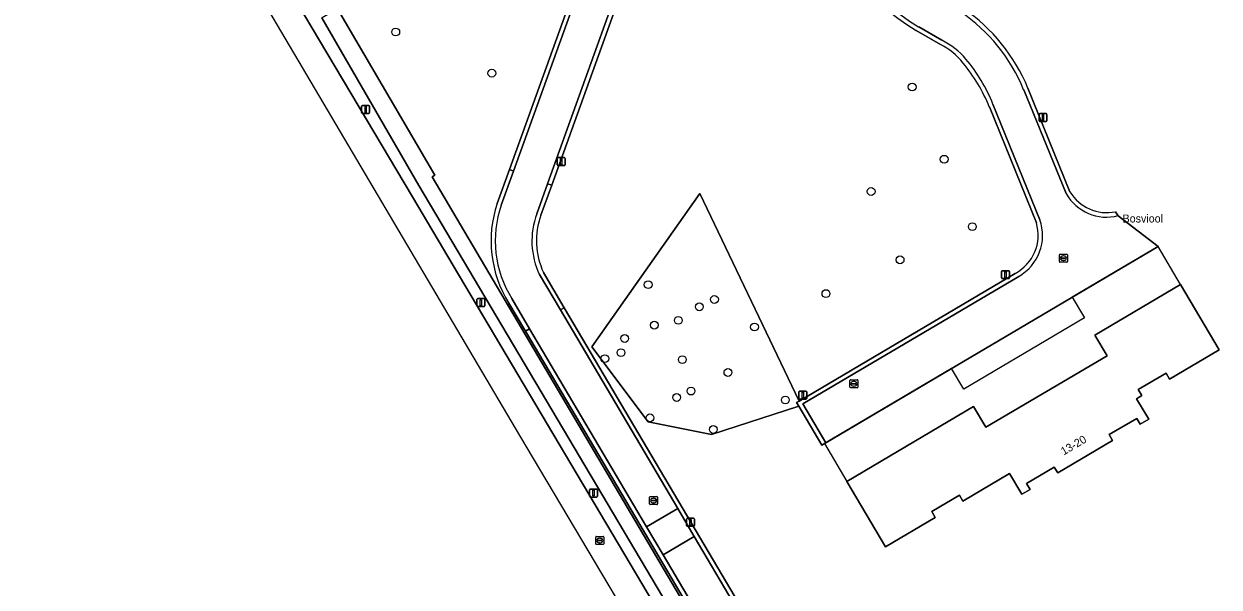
# Model space of a CAD drawing. Extents: x 156661 to 157576, y 383570 to 384425.
# Drawn here: x 156666.5 to 156815.9, y 383749.6 to 383820 of the extents above; entities that cross this region are included whole.
import ezdxf

# ---------------------------------------------------------------- set-up
doc = ezdxf.new("R2010")
doc.units = 0
for name, color, linetype in [('IMGEO_Boom', 7, 'Continuous'), ('IMGEO_Groenvoorziening', 7, 'Continuous'), ('IMGEO_Lichtmast', 7, 'Continuous'), ('IMGEO_Openbare_ruimte_label', 7, 'Continuous'), ('IMGEO_OVBaan_gesloten', 7, 'Continuous'), ('IMGEO_Pand', 7, 'Continuous'), ('IMGEO_Pand_nummerreeks', 7, 'Continuous'), ('IMGEO_Pand_overbouw', 7, 'Continuous'), ('IMGEO_Rijbaan_lokaal_gesloten', 7, 'Continuous'), ('IMGEO_Rijbaan_lokaal_halfverhard', 7, 'Continuous'), ('IMGEO_Rijbaan_lokaal_open', 7, 'Continuous'), ('IMGEO_Rioolput', 7, 'Continuous')]:
    doc.layers.add(name, color=color, linetype=linetype)

msp = doc.modelspace()

# ---------------------------------------------------------------- linework, layer by layer
at = {"layer": 'IMGEO_Boom'}
for centre in [(156712.98, 383818.98), (156724.99, 383813.83), (156777.53, 383812.1), (156781.53, 383803.07), (156772.4, 383799.04), (156785.05, 383794.64), (156776.02, 383790.49), (156744.54, 383787.39), (156766.75, 383786.27), (156750.93, 383784.62), (156752.82, 383785.54), (156745.31, 383782.32), (156748.3, 383782.92), (156757.82, 383782.1), (156741.59, 383780.66), (156741.13, 383778.89), (156739.12, 383778.14), (156748.8, 383778.01), (156754.5, 383776.41), (156749.89, 383774.08), (156748.09, 383773.28), (156761.67, 383772.97), (156744.76, 383770.73), (156752.67, 383769.28)]:
    msp.add_circle(centre, 0.489, dxfattribs=at)
at = {"layer": 'IMGEO_Groenvoorziening'}
for points in [[(156746.86, 383840.34), (156746.36, 383838.46), (156745.85, 383837.05), (156732.47, 383799.85), (156731.12, 383796.09)], [(156725.66, 383797.55), (156727.18, 383801.77), (156740.52, 383838.83)], [(156695.76, 383830.92), (156715.07, 383798.36), (156720.14, 383789.8), (156743.74, 383750), (156778.03, 383692.13), (156780.2, 383688.48), (156781.1, 383686.91)], [(156781.06, 383817.42), (156778.02, 383819.18)], [(156792.01, 383811.96), (156797.26, 383799.01)], [(156793.06, 383795.12), (156787.18, 383809.64)], [(156802.96, 383796.51), (156803.29, 383796.01), (156808.28, 383792.18), (156766.72, 383767.6), (156766.25, 383767.33), (156763.35, 383772.19), (156752.45, 383768.65), (156744.52, 383770.22), (156737.49, 383779.6), (156751, 383798.79), (156763.39, 383772.82), (156790.39, 383788.78)], [(156731.44, 383788.9), (156734.04, 383784.49), (156785.46, 383697.47), (156787.53, 383693.93)], [(156782.48, 383691.46), (156780.59, 383694.65), (156729.21, 383781.57), (156727.12, 383785.09)]]:
    msp.add_lwpolyline(points, dxfattribs=at)
for points in [[(156705.7, 383821.89), (156703.75, 383820.77), (156715.86, 383799.8), (156781.04, 383689.82), (156782.47, 383690.79), (156717.55, 383800.89), (156717.87, 383801.09)], [(156782.47, 383690.79), (156781.04, 383689.82), (156715.86, 383799.8), (156703.75, 383820.77), (156705.7, 383821.89), (156717.87, 383801.09), (156717.55, 383800.89)], [(156751, 383798.79), (156737.49, 383779.6), (156744.52, 383770.22), (156752.45, 383768.65), (156763.35, 383772.19), (156763.08, 383772.64), (156763.39, 383772.82)], [(156815.9, 383779.24), (156809.71, 383775.57), (156809.27, 383776.31), (156805.8, 383774.26), (156806.24, 383773.52), (156805.58, 383773.12), (156807.1, 383770.55), (156806.05, 383769.93), (156805.61, 383770.67), (156802.14, 383768.64), (156802.59, 383767.89), (156795.73, 383763.84), (156795.29, 383764.58), (156791.83, 383762.53), (156792.27, 383761.79), (156791.24, 383761.18), (156789.69, 383763.77), (156783.86, 383760.32), (156783.43, 383761.05), (156779.97, 383759.01), (156780.39, 383758.28), (156774.2, 383754.62), (156769.38, 383762.77), (156785.21, 383772.14), (156786.73, 383769.55), (156801.89, 383778.49), (156800.36, 383781.07), (156811.07, 383787.41)]]:
    msp.add_lwpolyline(points, close=True, dxfattribs=at)
for centre, radius, start, end in [((156793.47, 383844.76), 29.88, 157.8328, 238.869), ((156771.16, 383803.33), 22.56, 22.4904, 55.4335), ((156777.12, 383809.71), 8.66, 38.4985, 62.9776), ((156767.17, 383801.34), 21.66, 22.5311, 39.4519), ((156801.86, 383801.76), 5.36, 210.8749, 281.7523), ((156739.58, 383792.87), 14.69, 161.4197, 212.0138), ((156740.11, 383792.89), 9.54, 160.3934, 204.6888), ((156787.84, 383793.59), 5.44, 298.0182, 16.2918)]:
    msp.add_arc(centre, radius, start, end, dxfattribs=at)
at = {"layer": 'IMGEO_Lichtmast'}
for p, q in [((156708.72, 383808.9), (156708.72, 383809.7)), ((156708.72, 383809.7), (156708.72, 383808.9)), ((156708.82, 383809.8), (156709.61, 383809.8)), ((156709.61, 383809.8), (156708.82, 383809.8)), ((156709.71, 383809.7), (156709.71, 383808.9)), ((156709.71, 383808.9), (156709.71, 383809.7)), ((156709.61, 383808.8), (156708.82, 383808.8)), ((156708.82, 383808.8), (156709.61, 383808.8)), ((156793.39, 383807.89), (156793.39, 383808.68)), ((156793.39, 383808.68), (156793.39, 383807.89)), ((156793.49, 383808.78), (156794.28, 383808.78)), ((156794.28, 383808.78), (156793.49, 383808.78)), ((156794.28, 383807.79), (156793.49, 383807.79)), ((156793.49, 383807.79), (156794.28, 383807.79)), ((156794.38, 383808.68), (156794.38, 383807.89)), ((156794.38, 383807.89), (156794.38, 383808.68)), ((156733.17, 383802.38), (156733.17, 383803.18)), ((156733.17, 383803.18), (156733.17, 383802.38)), ((156733.27, 383803.28), (156734.06, 383803.28)), ((156734.06, 383803.28), (156733.27, 383803.28)), ((156734.16, 383803.18), (156734.16, 383802.38)), ((156734.16, 383802.38), (156734.16, 383803.18)), ((156734.06, 383802.28), (156733.27, 383802.28)), ((156733.27, 383802.28), (156734.06, 383802.28)), ((156788.7, 383788.24), (156788.7, 383789.03)), ((156788.7, 383789.03), (156788.7, 383788.24)), ((156788.8, 383789.13), (156789.59, 383789.13)), ((156789.59, 383789.13), (156788.8, 383789.13)), ((156789.59, 383788.14), (156788.8, 383788.14)), ((156788.8, 383788.14), (156789.59, 383788.14)), ((156789.69, 383789.03), (156789.69, 383788.24)), ((156789.69, 383788.24), (156789.69, 383789.03)), ((156723.13, 383784.74), (156723.13, 383785.54)), ((156723.13, 383785.54), (156723.13, 383784.74)), ((156723.23, 383785.64), (156724.01, 383785.64)), ((156724.01, 383785.64), (156723.23, 383785.64)), ((156724.11, 383785.54), (156724.11, 383784.74)), ((156724.11, 383784.74), (156724.11, 383785.54)), ((156724.01, 383784.64), (156723.23, 383784.64)), ((156723.23, 383784.64), (156724.01, 383784.64)), ((156763.36, 383773.17), (156763.36, 383773.97)), ((156763.36, 383773.97), (156763.36, 383773.17)), ((156763.46, 383774.07), (156764.25, 383774.07)), ((156764.25, 383774.07), (156763.46, 383774.07)), ((156764.25, 383773.07), (156763.46, 383773.07)), ((156763.46, 383773.07), (156764.25, 383773.07)), ((156764.35, 383773.97), (156764.35, 383773.17)), ((156764.35, 383773.17), (156764.35, 383773.97)), ((156737.2, 383760.93), (156737.2, 383761.73)), ((156737.2, 383761.73), (156737.2, 383760.93)), ((156737.3, 383761.83), (156738.09, 383761.83)), ((156738.09, 383761.83), (156737.3, 383761.83)), ((156738.19, 383761.73), (156738.19, 383760.93)), ((156738.19, 383760.93), (156738.19, 383761.73)), ((156738.09, 383760.83), (156737.3, 383760.83)), ((156737.3, 383760.83), (156738.09, 383760.83)), ((156749.42, 383758.17), (156750.21, 383758.17)), ((156750.21, 383758.17), (156749.42, 383758.17)), ((156749.32, 383757.27), (156749.32, 383758.07)), ((156749.32, 383758.07), (156749.32, 383757.27)), ((156750.21, 383757.17), (156749.42, 383757.17)), ((156749.42, 383757.17), (156750.21, 383757.17)), ((156750.31, 383758.07), (156750.31, 383757.27)), ((156750.31, 383757.27), (156750.31, 383758.07))]:
    msp.add_line(p, q, dxfattribs=at)
for points in [[(156709.14, 383809.67), (156709.29, 383809.67), (156709.29, 383808.92), (156709.14, 383808.92), (156709.14, 383809.67)], [(156793.81, 383808.66), (156793.96, 383808.66), (156793.96, 383807.91), (156793.81, 383807.91), (156793.81, 383808.66)], [(156733.59, 383803.15), (156733.74, 383803.15), (156733.74, 383802.4), (156733.59, 383802.4), (156733.59, 383803.15)], [(156789.12, 383789.01), (156789.27, 383789.01), (156789.27, 383788.26), (156789.12, 383788.26), (156789.12, 383789.01)], [(156723.54, 383785.51), (156723.7, 383785.51), (156723.7, 383784.76), (156723.54, 383784.76), (156723.54, 383785.51)], [(156763.78, 383773.95), (156763.93, 383773.95), (156763.93, 383773.2), (156763.78, 383773.2), (156763.78, 383773.95)], [(156737.62, 383761.71), (156737.77, 383761.71), (156737.77, 383760.96), (156737.62, 383760.96), (156737.62, 383761.71)], [(156749.74, 383758.04), (156749.89, 383758.04), (156749.89, 383757.29), (156749.74, 383757.29), (156749.74, 383758.04)]]:
    msp.add_lwpolyline(points, dxfattribs=at)
for centre, start, end in [((156708.82, 383809.7), 90, 180), ((156708.82, 383809.7), 90, 180), ((156708.82, 383808.9), 180, 270), ((156708.82, 383808.9), 180, 270), ((156709.61, 383809.7), 0, 90), ((156709.61, 383809.7), 360, 90), ((156709.61, 383808.9), 270, 0), ((156709.61, 383808.9), 270, 0), ((156793.49, 383808.68), 90, 180), ((156793.49, 383808.68), 90, 180), ((156793.49, 383807.89), 180, 270), ((156793.49, 383807.89), 180, 270), ((156794.28, 383808.68), 0, 90), ((156794.28, 383808.68), 360, 90), ((156794.28, 383807.89), 270, 0), ((156794.28, 383807.89), 270, 0), ((156733.27, 383803.18), 90, 180), ((156733.27, 383803.18), 90, 180), ((156734.06, 383803.18), 0, 90), ((156734.06, 383803.18), 360, 90), ((156733.27, 383802.38), 180, 270), ((156733.27, 383802.38), 180, 270), ((156734.06, 383802.38), 270, 0), ((156734.06, 383802.38), 270, 0), ((156788.8, 383789.03), 90, 180), ((156788.8, 383789.03), 90, 180), ((156788.8, 383788.24), 180, 270), ((156788.8, 383788.24), 180, 270), ((156789.59, 383789.03), 0, 90), ((156789.59, 383789.03), 360, 90), ((156789.59, 383788.24), 270, 0), ((156789.59, 383788.24), 270, 0), ((156723.23, 383785.54), 90, 180), ((156723.23, 383785.54), 90, 180), ((156724.01, 383785.54), 0, 90), ((156724.01, 383785.54), 360, 90), ((156723.23, 383784.74), 180, 270), ((156723.23, 383784.74), 180, 270), ((156724.01, 383784.74), 270, 0), ((156724.01, 383784.74), 270, 0), ((156763.46, 383773.97), 90, 180), ((156763.46, 383773.97), 90, 180), ((156763.46, 383773.17), 180, 270), ((156763.46, 383773.17), 180, 270), ((156764.25, 383773.97), 0, 90), ((156764.25, 383773.97), 360, 90), ((156764.25, 383773.17), 270, 0), ((156764.25, 383773.17), 270, 0), ((156737.3, 383761.73), 90, 180), ((156737.3, 383761.73), 90, 180), ((156738.09, 383761.73), 0, 90), ((156738.09, 383761.73), 360, 90), ((156737.3, 383760.93), 180, 270), ((156737.3, 383760.93), 180, 270), ((156738.09, 383760.93), 270, 0), ((156738.09, 383760.93), 270, 0), ((156749.42, 383758.07), 90, 180), ((156749.42, 383758.07), 90, 180), ((156750.21, 383758.07), 0, 90), ((156750.21, 383758.07), 360, 90), ((156749.42, 383757.27), 180, 270), ((156749.42, 383757.27), 180, 270), ((156750.21, 383757.27), 270, 0), ((156750.21, 383757.27), 270, 0)]:
    msp.add_arc(centre, 0.1, start, end, dxfattribs=at)
at = {"layer": 'IMGEO_OVBaan_gesloten'}
msp.add_lwpolyline([(156774.68, 383690.66), (156778.03, 383692.13), (156743.74, 383750), (156720.14, 383789.8), (156715.07, 383798.36), (156695.76, 383830.92), (156695.87, 383831), (156695.25, 383832.05), (156693.6, 383834.8), (156692.04, 383837.4), (156678.24, 383860.71), (156676.83, 383863.03), (156675.34, 383865.46), (156674.75, 383866.42), (156673.06, 383869.24), (156673, 383869.08), (156671.26, 383871.72), (156669.54, 383874.35), (156666.5, 383872.69), (156669.04, 383869), (156694.5, 383826.07), (156728.44, 383768.53)], close=True, dxfattribs=at)
at = {"layer": 'IMGEO_Pand'}
msp.add_lwpolyline([(156805.61, 383770.67), (156806.05, 383769.93), (156807.1, 383770.55), (156805.58, 383773.12), (156806.24, 383773.52), (156805.8, 383774.26), (156809.27, 383776.31), (156809.71, 383775.57), (156815.9, 383779.24), (156811.07, 383787.41), (156800.36, 383781.07), (156801.89, 383778.49), (156786.73, 383769.55), (156785.21, 383772.14), (156769.38, 383762.77), (156774.2, 383754.62), (156780.39, 383758.28), (156779.97, 383759.01), (156783.43, 383761.05), (156783.86, 383760.32), (156789.69, 383763.77), (156791.24, 383761.18), (156792.27, 383761.79), (156791.83, 383762.53), (156795.29, 383764.58), (156795.73, 383763.84), (156802.59, 383767.89), (156802.14, 383768.64)], close=True, dxfattribs=at)
at = {"layer": 'IMGEO_Pand_overbouw'}
msp.add_lwpolyline([(156808.27, 383792.17), (156797.55, 383785.84), (156799.07, 383783.25), (156783.98, 383774.32), (156782.46, 383776.91), (156766.58, 383767.51), (156769.38, 383762.77), (156785.21, 383772.14), (156786.73, 383769.55), (156801.89, 383778.49), (156800.36, 383781.07), (156811.07, 383787.41)], close=True, dxfattribs=at)
at = {"layer": 'IMGEO_Rijbaan_lokaal_gesloten'}
for points in [[(156781.24, 383817.96), (156778.35, 383819.61)], [(156778.02, 383819.18), (156781.06, 383817.42)], [(156797.26, 383799.01), (156792.01, 383811.96)], [(156791.47, 383811.75), (156796.79, 383798.78)], [(156787.18, 383809.64), (156793.06, 383795.12)], [(156793.48, 383795.5), (156787.63, 383809.96)], [(156726.17, 383797.34), (156727.71, 383801.6), (156727.18, 383801.77), (156725.66, 383797.55)], [(156731.12, 383796.09), (156732.47, 383799.85), (156731.95, 383799.99), (156730.6, 383796.25)], [(156803.29, 383796.01), (156802.96, 383796.51)], [(156730.96, 383788.64), (156733.57, 383784.22), (156734.04, 383784.49), (156731.44, 383788.9)], [(156790.39, 383788.78), (156763.39, 383772.82), (156763.08, 383772.64), (156763.35, 383772.19), (156766.25, 383767.33), (156766.72, 383767.6), (156763.88, 383772.47), (156790.85, 383788.42)], [(156727.12, 383785.09), (156729.21, 383781.57), (156729.71, 383781.87), (156727.49, 383785.64)]]:
    msp.add_lwpolyline(points, dxfattribs=at)
for centre, radius, start, end in [((156793.47, 383844.76), 29.88, 157.8328, 238.869), ((156793.86, 383844.98), 29.74, 158.5089, 238.5458), ((156771.39, 383803.57), 21.68, 22.1754, 55.809), ((156771.16, 383803.33), 22.56, 22.4904, 55.4335), ((156776.88, 383809.33), 9.67, 40.2671, 63.1821), ((156777.12, 383809.71), 8.66, 38.4985, 62.9776), ((156767.17, 383801.34), 21.66, 22.5311, 39.4519), ((156768.93, 383802.56), 20.11, 21.5898, 40.3527), ((156801.83, 383801.62), 5.79, 209.4152, 284.5476), ((156801.86, 383801.76), 5.36, 210.8749, 281.7523), ((156739.58, 383792.87), 14.69, 161.4197, 212.0138), ((156739.15, 383792.88), 13.73, 161.0194, 211.8307), ((156739.77, 383792.86), 9.77, 159.7121, 205.6139), ((156740.11, 383792.89), 9.54, 160.3934, 204.6888), ((156787.98, 383793.52), 5.85, 299.3486, 19.827), ((156787.84, 383793.59), 5.44, 298.0182, 16.2918)]:
    msp.add_arc(centre, radius, start, end, dxfattribs=at)
at = {"layer": 'IMGEO_Rijbaan_lokaal_halfverhard'}
for points in [[(156741.04, 383838.63), (156740.52, 383838.83), (156727.18, 383801.77), (156727.71, 383801.6)], [(156745.85, 383837.05), (156745.32, 383837.24), (156731.95, 383799.99), (156732.47, 383799.85)], [(156734.04, 383784.49), (156733.57, 383784.22), (156748.22, 383759.41), (156750.3, 383755.89), (156784.96, 383697.2), (156785.46, 383697.47)], [(156729.71, 383781.87), (156729.21, 383781.57), (156780.59, 383694.65), (156781.03, 383694.93), (156746.4, 383753.6), (156744.34, 383757.09)]]:
    msp.add_lwpolyline(points, close=True, dxfattribs=at)
at = {"layer": 'IMGEO_Rijbaan_lokaal_open'}
for points in [[(156741.65, 383840.3), (156741.04, 383838.63), (156727.71, 383801.6), (156726.17, 383797.34)], [(156730.6, 383796.25), (156731.95, 383799.99), (156745.32, 383837.24)], [(156778.35, 383819.61), (156781.24, 383817.96)], [(156796.79, 383798.78), (156791.47, 383811.75)], [(156787.63, 383809.96), (156793.48, 383795.5)], [(156790.85, 383788.42), (156763.88, 383772.47), (156766.72, 383767.6), (156808.28, 383792.18), (156803.29, 383796.01)], [(156727.49, 383785.64), (156729.71, 383781.87), (156744.34, 383757.09), (156748.22, 383759.41), (156733.57, 383784.22), (156730.96, 383788.64)], [(156786.86, 383693.97), (156784.96, 383697.2), (156750.3, 383755.89), (156746.4, 383753.6), (156781.03, 383694.93), (156783.31, 383691.07)]]:
    msp.add_lwpolyline(points, dxfattribs=at)
msp.add_lwpolyline([(156748.22, 383759.41), (156744.34, 383757.09), (156746.4, 383753.6), (156750.3, 383755.89)], close=True, dxfattribs=at)
for centre, radius, start, end in [((156793.86, 383844.98), 29.74, 158.5089, 238.5458), ((156771.39, 383803.57), 21.68, 22.1754, 55.809), ((156776.88, 383809.33), 9.67, 40.2671, 63.1821), ((156768.93, 383802.56), 20.11, 21.5898, 40.3527), ((156801.83, 383801.62), 5.79, 209.4152, 284.5476), ((156739.15, 383792.88), 13.73, 161.0194, 211.8307), ((156739.77, 383792.86), 9.77, 159.7121, 205.6139), ((156787.98, 383793.52), 5.85, 299.3486, 19.827)]:
    msp.add_arc(centre, radius, start, end, dxfattribs=at)
at = {"layer": 'IMGEO_Rioolput'}
for p, q in [((156795.94, 383790.27), (156795.94, 383791.12)), ((156796.01, 383791.2), (156796.86, 383791.2)), ((156796.43, 383790.98), (156796.45, 383790.98)), ((156796.94, 383791.12), (156796.94, 383790.27)), ((156796.86, 383790.2), (156796.01, 383790.2)), ((156796.2, 383790.69), (156796.2, 383790.7)), ((156796.24, 383790.74), (156796.64, 383790.74)), ((156796.63, 383790.65), (156796.24, 383790.65)), ((156796.45, 383790.42), (156796.42, 383790.42)), ((156796.68, 383790.7), (156796.68, 383790.69)), ((156769.75, 383774.57), (156769.75, 383775.42)), ((156769.82, 383775.5), (156770.67, 383775.5)), ((156770, 383774.99), (156770, 383775)), ((156770.44, 383774.95), (156770.04, 383774.95)), ((156770.05, 383775.04), (156770.44, 383775.04)), ((156770.23, 383775.27), (156770.26, 383775.27)), ((156770.26, 383774.72), (156770.23, 383774.72)), ((156770.49, 383775), (156770.49, 383774.99)), ((156770.75, 383775.42), (156770.75, 383774.57)), ((156770.67, 383774.49), (156769.82, 383774.49)), ((156744.71, 383759.97), (156744.71, 383760.82)), ((156744.78, 383760.89), (156745.63, 383760.89)), ((156745.63, 383759.89), (156744.78, 383759.89)), ((156744.96, 383760.39), (156744.96, 383760.4)), ((156745.4, 383760.35), (156745, 383760.35)), ((156745.01, 383760.44), (156745.4, 383760.44)), ((156745.19, 383760.67), (156745.22, 383760.67)), ((156745.22, 383760.11), (156745.19, 383760.11)), ((156745.45, 383760.4), (156745.45, 383760.39)), ((156745.71, 383760.82), (156745.71, 383759.97)), ((156737.98, 383754.97), (156737.98, 383755.82)), ((156738.05, 383755.89), (156738.91, 383755.89)), ((156738.24, 383755.39), (156738.24, 383755.4)), ((156738.28, 383755.44), (156738.68, 383755.44)), ((156738.67, 383755.35), (156738.28, 383755.35)), ((156738.47, 383755.67), (156738.49, 383755.67)), ((156738.72, 383755.4), (156738.72, 383755.39)), ((156738.98, 383755.82), (156738.98, 383754.97)), ((156738.91, 383754.89), (156738.05, 383754.89)), ((156738.49, 383755.11), (156738.46, 383755.11))]:
    msp.add_line(p, q, dxfattribs=at)
for points in [[(156795.94, 383790.27), (156795.94, 383791.12)], [(156796.01, 383791.2), (156796.86, 383791.2)], [(156796.94, 383791.12), (156796.94, 383790.27)], [(156796.86, 383790.2), (156796.01, 383790.2)], [(156769.75, 383774.57), (156769.75, 383775.42)], [(156769.82, 383775.5), (156770.67, 383775.5)], [(156770.75, 383775.42), (156770.75, 383774.57)], [(156770.67, 383774.49), (156769.82, 383774.49)], [(156744.71, 383759.97), (156744.71, 383760.82)], [(156744.78, 383760.89), (156745.63, 383760.89)], [(156745.63, 383759.89), (156744.78, 383759.89)], [(156745.71, 383760.82), (156745.71, 383759.97)], [(156737.98, 383754.97), (156737.98, 383755.82)], [(156738.05, 383755.89), (156738.91, 383755.89)], [(156738.98, 383755.82), (156738.98, 383754.97)], [(156738.91, 383754.89), (156738.05, 383754.89)]]:
    msp.add_lwpolyline(points, dxfattribs=at)
for centre, radius, start, end in [((156796.01, 383791.12), 0.0765, 91.552, 178.448), ((156796.01, 383791.12), 0.0765, 91.552, 178.448), ((156796.86, 383791.12), 0.0765, 1.552, 88.448), ((156796.86, 383791.12), 0.0765, 1.552, 88.448), ((156796.01, 383790.27), 0.0765, 181.552, 268.448), ((156796.01, 383790.27), 0.0765, 181.552, 268.448), ((156796.24, 383790.7), 0.0403, 85.8775, 175.7526), ((156796.23, 383790.69), 0.0366, 178.938, 274.7102), ((156796.64, 383790.7), 0.043, 264.8664, 352.4533), ((156796.64, 383790.7), 0.0386, 1.7309, 96.639), ((156796.86, 383790.27), 0.0765, 271.552, 358.448), ((156796.86, 383790.27), 0.0765, 271.552, 358.448), ((156769.82, 383775.42), 0.0765, 91.552, 178.448), ((156769.82, 383775.42), 0.0765, 91.552, 178.448), ((156769.82, 383774.57), 0.0765, 181.552, 268.448), ((156769.82, 383774.57), 0.0765, 181.552, 268.448), ((156770.04, 383775), 0.0403, 85.8775, 175.7526), ((156770.04, 383774.99), 0.0366, 178.938, 274.7102), ((156770.45, 383775), 0.0386, 1.7309, 96.639), ((156770.45, 383774.99), 0.043, 264.8664, 352.4533), ((156770.67, 383775.42), 0.0765, 1.552, 88.448), ((156770.67, 383775.42), 0.0765, 1.552, 88.448), ((156770.67, 383774.57), 0.0765, 271.552, 358.448), ((156770.67, 383774.57), 0.0765, 271.552, 358.448), ((156744.78, 383760.82), 0.0765, 91.552, 178.448), ((156744.78, 383760.82), 0.0765, 91.552, 178.448), ((156744.78, 383759.97), 0.0765, 181.552, 268.448), ((156744.78, 383759.97), 0.0765, 181.552, 268.448), ((156745, 383760.4), 0.0403, 85.8775, 175.7526), ((156745, 383760.39), 0.0366, 178.938, 274.7102), ((156745.41, 383760.4), 0.0386, 1.7309, 96.639), ((156745.41, 383760.39), 0.043, 264.8664, 352.4533), ((156745.63, 383760.82), 0.0765, 1.552, 88.448), ((156745.63, 383760.82), 0.0765, 1.552, 88.448), ((156745.63, 383759.97), 0.0765, 271.552, 358.448), ((156745.63, 383759.97), 0.0765, 271.552, 358.448), ((156738.05, 383755.82), 0.0765, 91.552, 178.448), ((156738.05, 383755.82), 0.0765, 91.552, 178.448), ((156738.28, 383755.4), 0.0403, 85.8775, 175.7526), ((156738.27, 383755.39), 0.0366, 178.938, 274.7102), ((156738.68, 383755.39), 0.043, 264.8664, 352.4533), ((156738.68, 383755.4), 0.0386, 1.7309, 96.639), ((156738.9, 383755.82), 0.0765, 1.552, 88.448), ((156738.9, 383755.82), 0.0765, 1.552, 88.448), ((156738.05, 383754.97), 0.0765, 181.552, 268.448), ((156738.05, 383754.97), 0.0765, 181.552, 268.448), ((156738.9, 383754.97), 0.0765, 271.552, 358.448), ((156738.9, 383754.97), 0.0765, 271.552, 358.448)]:
    msp.add_arc(centre, radius, start, end, dxfattribs=at)
for centre, major_axis, ratio, start_param, end_param in [((156796.42, 383790.7), (-0.387, 0.002), 0.722429, 4.712389, 7.853982), ((156796.45, 383790.7), (-0.39, 0.002), 0.717154, 1.570796, 4.712389), ((156770.23, 383774.99), (-0.387, 0.002), 0.722429, 4.712389, 7.853982), ((156770.26, 383774.99), (-0.39, 0.002), 0.717154, 1.570796, 4.712389), ((156745.19, 383760.39), (-0.387, 0.002), 0.722429, 4.712389, 7.853982), ((156745.22, 383760.39), (-0.39, 0.002), 0.717154, 1.570796, 4.712389), ((156738.47, 383755.39), (-0.387, 0.002), 0.722429, 4.712389, 7.853982), ((156738.49, 383755.39), (-0.39, 0.002), 0.717154, 1.570796, 4.712389)]:
    msp.add_ellipse(centre, major_axis=major_axis, ratio=ratio, start_param=start_param, end_param=end_param, dxfattribs=at)

# ---------------------------------------------------------------- texts
at = {"layer": 'IMGEO_Openbare_ruimte_label'}
msp.add_text('Bosviool', height=1, dxfattribs=at).set_placement((156803.83, 383795.16))
at = {"layer": 'IMGEO_Pand_nummerreeks'}
msp.add_text('13-20', height=1, rotation=30.5673, dxfattribs=at).set_placement((156796.48, 383766.02))

doc.saveas('drawing.dxf')
